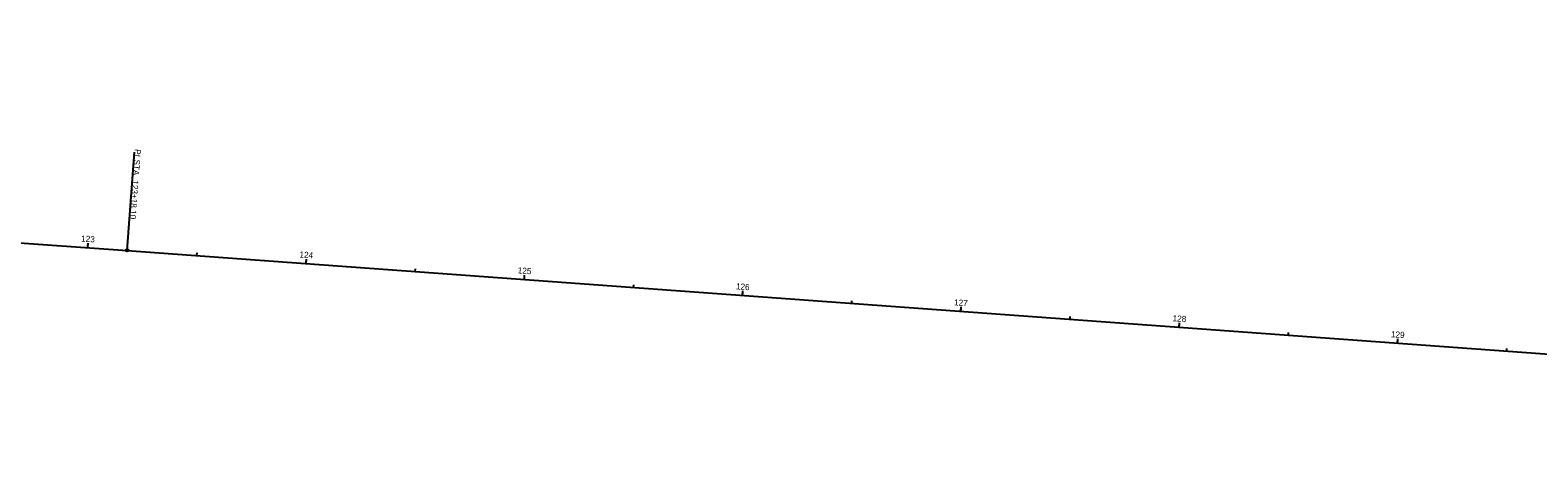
# Model space of a CAD drawing. Extents: x 1898401 to 1901169, y 703131 to 703379.
# Drawn here: x 1899771 to 1900460, y 703131 to 703330 of the extents above; entities that cross this region are included whole.
import ezdxf

# ---------------------------------------------------------------- set-up
doc = ezdxf.new("R2010")
doc.units = 0
for name, color, linetype in [('RW_X_CL', 7, 'Continuous'), ('RW_X_CL_1000_Cardinal_Points', 7, 'Continuous'), ('RW_X_CL_1000_Stations', 7, 'Continuous'), ('RW_X_CL_100_Cardinal_Points', 7, 'Continuous'), ('RW_X_CL_100_Stations', 7, 'Continuous'), ('RW_X_CL_500_Cardinal_Points', 7, 'Continuous'), ('RW_X_CL_500_Stations', 7, 'Continuous')]:
    doc.layers.add(name, color=color, linetype=linetype)

msp = doc.modelspace()

# ---------------------------------------------------------------- linework, layer by layer
at = {"layer": 'RW_X_CL'}
for p, q in [((1898401.58, 703330.4), (1899815.76, 703229.84)), ((1899815.76, 703229.84), (1901162.17, 703131.42))]:
    msp.add_line(p, q, dxfattribs=at)
at = {"layer": 'RW_X_CL_1000_Cardinal_Points'}
msp.add_line((1899815.76, 703229.84), (1899819.04, 703274.72), dxfattribs=at)
msp.add_circle((1899815.76, 703229.84), 0.6, dxfattribs=at)
at = {"layer": 'RW_X_CL_1000_Stations'}
msp.add_line((1899997.18, 703216.58), (1899997.26, 703217.77), dxfattribs=at)
at = {"layer": 'RW_X_CL_100_Cardinal_Points'}
msp.add_line((1899815.76, 703229.84), (1899819.04, 703274.72), dxfattribs=at)
msp.add_circle((1899815.76, 703229.84), 0.6, dxfattribs=at)
at = {"layer": 'RW_X_CL_100_Stations'}
for p, q in [((1899797.71, 703231.12), (1899797.85, 703233.12)), ((1899847.58, 703227.51), (1899847.66, 703228.71)), ((1899897.44, 703223.87), (1899897.59, 703225.86)), ((1899947.31, 703220.22), (1899947.4, 703221.42)), ((1899997.18, 703216.58), (1899997.32, 703218.57)), ((1900047.04, 703212.93), (1900047.13, 703214.13)), ((1900096.91, 703209.29), (1900097.06, 703211.28)), ((1900146.78, 703205.64), (1900146.87, 703206.84)), ((1900196.64, 703202), (1900196.79, 703203.99)), ((1900246.51, 703198.35), (1900246.6, 703199.55)), ((1900296.38, 703194.71), (1900296.52, 703196.7)), ((1900346.25, 703191.06), (1900346.33, 703192.26)), ((1900396.11, 703187.42), (1900396.26, 703189.41)), ((1900445.98, 703183.77), (1900446.07, 703184.97))]:
    msp.add_line(p, q, dxfattribs=at)
at = {"layer": 'RW_X_CL_500_Cardinal_Points'}
msp.add_line((1899815.76, 703229.84), (1899819.04, 703274.72), dxfattribs=at)
msp.add_circle((1899815.76, 703229.84), 0.6, dxfattribs=at)
at = {"layer": 'RW_X_CL_500_Stations'}
for p, q in [((1899797.71, 703231.12), (1899797.79, 703232.32)), ((1899897.44, 703223.87), (1899897.53, 703225.07)), ((1899997.18, 703216.58), (1899997.32, 703218.57)), ((1900096.91, 703209.29), (1900097, 703210.48)), ((1900196.64, 703202), (1900196.73, 703203.19)), ((1900296.38, 703194.71), (1900296.47, 703195.9)), ((1900396.11, 703187.42), (1900396.2, 703188.61))]:
    msp.add_line(p, q, dxfattribs=at)

# ---------------------------------------------------------------- texts
at = {"layer": 'RW_X_CL_1000_Cardinal_Points'}
for s, p in [(' STA. ', (1899818.93, 703272.48)), ('PI', (1899819.2, 703276.16)), ('123+18.10', (1899818.16, 703261.93))]:
    msp.add_text(s, height=2.8, rotation=265.81918, dxfattribs=at).set_placement(p)
at = {"layer": 'RW_X_CL_100_Cardinal_Points'}
for s, p in [(' STA. ', (1899818.93, 703272.48)), ('PI', (1899819.2, 703276.16)), ('123+18.10', (1899818.16, 703261.93))]:
    msp.add_text(s, height=2.8, rotation=265.81918, dxfattribs=at).set_placement(p)
at = {"layer": 'RW_X_CL_100_Stations'}
for s, rotation, p in [('123', 355.93252, (1899794.62, 703233.89)), ('124', 355.81918, (1899894.36, 703226.61)), ('125', 355.81918, (1899994.07, 703219.35)), ('126', 355.81918, (1900093.75, 703212.07)), ('127', 355.81918, (1900193.42, 703204.75)), ('128', 355.81918, (1900293.24, 703197.49)), ('129', 355.81918, (1900392.99, 703190.19))]:
    msp.add_text(s, height=2.8, rotation=rotation, dxfattribs=at).set_placement(p)
at = {"layer": 'RW_X_CL_500_Cardinal_Points'}
for s, p in [(' STA. ', (1899818.93, 703272.48)), ('PI', (1899819.2, 703276.16)), ('123+18.10', (1899818.16, 703261.93))]:
    msp.add_text(s, height=2.8, rotation=265.81918, dxfattribs=at).set_placement(p)
at = {"layer": 'RW_X_CL_500_Stations'}
msp.add_text('125', height=2.8, rotation=355.81918, dxfattribs=at).set_placement((1899994.07, 703219.35))

doc.saveas('drawing.dxf')
